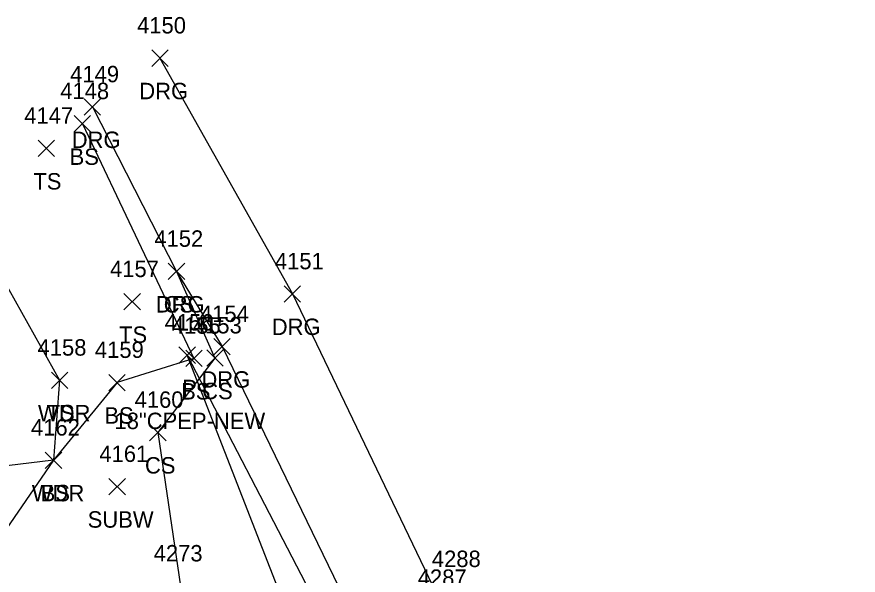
# Model space of a CAD drawing. Extents: x 49137 to 50946, y 9590 to 10709.
# Drawn here: x 50101.6 to 50204, y 10636.8 to 10704.8 of the extents above; entities that cross this region are included whole.
import ezdxf

# ---------------------------------------------------------------- set-up
doc = ezdxf.new("R2010")
doc.units = 0
for name, color, linetype in [('D_A', 7, 'Continuous'), ('D_C', 7, 'Continuous'), ('D_I', 7, 'Continuous'), ('D_TIC', 7, 'Continuous'), ('DCP', 7, 'Continuous'), ('L_A', 7, 'Continuous'), ('L_I', 7, 'Continuous'), ('L_TIC', 7, 'Continuous'), ('LAWA', 7, 'Continuous'), ('LELB', 7, 'Continuous'), ('R_A', 7, 'Continuous'), ('R_I', 7, 'Continuous'), ('R_TIC', 7, 'Continuous'), ('RDG', 7, 'Continuous'), ('U_A', 7, 'Continuous'), ('U_I', 7, 'Continuous'), ('U_TIC', 7, 'Continuous')]:
    doc.layers.add(name, color=color, linetype=linetype)

msp = doc.modelspace()

# ---------------------------------------------------------------- linework, layer by layer
at = {"layer": 'D_TIC'}
for points in [[(50121.34, 10662.61), (50123.34, 10664.61)], [(50123.34, 10662.61), (50121.34, 10664.61)]]:
    msp.add_lwpolyline(points, dxfattribs=at)
at = {"layer": 'DCP'}
msp.add_lwpolyline([(49941.69, 9827.48), (50059.34, 9808.37), (50181.4, 9733.09), (50281.74, 9743.29), (50422.72, 9892.52), (50122.34, 10663.61), (50179.93, 10552.61), (50179.64, 10394.45), (50122.34, 10285.07), (50121.56, 10284.35)], dxfattribs=at)
at = {"layer": 'L_TIC'}
for points in [[(50108.59, 10690.77), (50110.59, 10692.77)], [(50110.59, 10690.77), (50108.59, 10692.77)], [(50104.21, 10687.77), (50106.21, 10689.77)], [(50106.21, 10687.77), (50104.21, 10689.77)], [(50120.04, 10672.8), (50122.04, 10674.8)], [(50122.04, 10672.8), (50120.04, 10674.8)], [(50114.64, 10669.11), (50116.64, 10671.11)], [(50116.64, 10669.11), (50114.64, 10671.11)], [(50122.16, 10662.21), (50124.16, 10664.21)], [(50124.16, 10662.21), (50122.16, 10664.21)], [(50124.72, 10662.25), (50126.72, 10664.25)], [(50126.72, 10662.25), (50124.72, 10664.25)], [(50105.82, 10659.55), (50107.82, 10661.55)], [(50107.82, 10659.55), (50105.82, 10661.55)], [(50105.82, 10659.55), (50107.82, 10661.55)], [(50107.82, 10659.55), (50105.82, 10661.55)], [(50112.81, 10659.27), (50114.81, 10661.27)], [(50114.81, 10659.27), (50112.81, 10661.27)], [(50117.76, 10653.2), (50119.76, 10655.2)], [(50119.76, 10653.2), (50117.76, 10655.2)], [(50105.07, 10649.82), (50107.07, 10651.82)], [(50107.07, 10649.82), (50105.07, 10651.82)], [(50105.07, 10649.82), (50107.07, 10651.82)], [(50107.07, 10649.82), (50105.07, 10651.82)]]:
    msp.add_lwpolyline(points, dxfattribs=at)
at = {"layer": 'LAWA'}
msp.add_lwpolyline([(50094.44, 10682.64), (50106.82, 10660.55), (50106.07, 10650.82), (50096.35, 10649.67)], dxfattribs=at)
at = {"layer": 'LELB'}
for points in [[(50109.59, 10691.77), (50123.16, 10663.21), (50113.81, 10660.27), (50106.07, 10650.82), (50097.87, 10638.93), (50087.99, 10629.91)], [(50121.04, 10673.8), (50125.72, 10663.25), (50118.76, 10654.2), (50121.52, 10635.5), (50130.84, 10628.15), (50141.37, 10625.76), (50142.8, 10621.81), (50131.45, 10616.61), (50128.86, 10614.81), (50135.94, 10599.09), (50146.92, 10581.6), (50169.4, 10551.93), (50172.24, 10543.56), (50191.94, 10521.73), (50208.27, 10509.79)]]:
    msp.add_lwpolyline(points, dxfattribs=at)
at = {"layer": 'R_TIC'}
for points in [[(50118.02, 10698.76), (50120.02, 10700.76)], [(50120.02, 10698.76), (50118.02, 10700.76)], [(50109.8, 10692.82), (50111.8, 10694.82)], [(50111.8, 10692.82), (50109.8, 10694.82)], [(50120.04, 10672.8), (50122.04, 10674.8)], [(50122.04, 10672.8), (50120.04, 10674.8)], [(50134.14, 10670.06), (50136.14, 10672.06)], [(50136.14, 10670.06), (50134.14, 10672.06)], [(50125.58, 10663.65), (50127.58, 10665.65)], [(50127.58, 10663.65), (50125.58, 10665.65)]]:
    msp.add_lwpolyline(points, dxfattribs=at)
at = {"layer": 'RDG'}
for points in [[(50119.02, 10699.76), (50135.14, 10671.06), (50153.64, 10632.53), (50170.9, 10598.36), (50195.96, 10553.2), (50209.41, 10536.57), (50218.43, 10521.85), (50227.96, 10501.32), (50227.51, 10456.11), (50228.06, 10435.89), (50234.37, 10417.11), (50265.83, 10427.19)], [(50110.8, 10693.82), (50121.04, 10673.8), (50126.58, 10664.65), (50145.31, 10626.1), (50162.07, 10592.03), (50186.9, 10549.34), (50201.97, 10525.51), (50210.44, 10510.19), (50215.05, 10493.61), (50214.49, 10487.12), (50214.47, 10480.19), (50214.66, 10477.36), (50207.53, 10457)]]:
    msp.add_lwpolyline(points, dxfattribs=at)
at = {"layer": 'U_TIC'}
for points in [[(50112.82, 10646.61), (50114.82, 10648.61)], [(50114.82, 10646.61), (50112.82, 10648.61)]]:
    msp.add_lwpolyline(points, dxfattribs=at)

# ---------------------------------------------------------------- texts
at = {"layer": 'D_A'}
msp.add_text('P', height=2, dxfattribs=at).set_placement((50121.72, 10658.61))
at = {"layer": 'D_C'}
msp.add_text('18"CPEP-NEW', height=2, dxfattribs=at).set_placement((50113.49, 10654.61))
at = {"layer": 'D_I'}
for s, p in [('4156', (50119.59, 10666.61)), ('4288', (50152.11, 10637.82))]:
    msp.add_text(s, height=2, dxfattribs=at).set_placement(p)
at = {"layer": 'L_A'}
for s, p in [('BS', (50108.03, 10686.77)), ('TS', (50103.62, 10683.77)), ('CS', (50119.48, 10668.8)), ('TS', (50114.05, 10665.11)), ('BS', (50121.6, 10658.21)), ('CS', (50124.16, 10658.25)), ('WDR', (50104.18, 10655.55)), ('TS', (50105.23, 10655.55)), ('BS', (50112.26, 10655.27)), ('CS', (50117.2, 10649.2)), ('WDR', (50103.43, 10645.82)), ('BS', (50104.51, 10645.82))]:
    msp.add_text(s, height=2, dxfattribs=at).set_placement(p)
at = {"layer": 'L_I'}
for s, p in [('4148', (50106.89, 10694.77)), ('4147', (50102.51, 10691.77)), ('4152', (50118.34, 10676.8)), ('4157', (50112.95, 10673.11)), ('4155', (50120.47, 10666.21)), ('4153', (50123.03, 10666.25)), ('4158', (50104.13, 10663.55)), ('4158', (50104.13, 10663.55)), ('4159', (50111.11, 10663.27)), ('4160', (50115.94, 10657.2)), ('4162', (50103.33, 10653.82)), ('4162', (50103.33, 10653.82)), ('4273', (50118.26, 10638.5)), ('4273', (50118.26, 10638.5))]:
    msp.add_text(s, height=2, dxfattribs=at).set_placement(p)
at = {"layer": 'R_A'}
for p in [(50116.51, 10694.76), (50108.29, 10688.82), (50118.52, 10668.8), (50132.63, 10666.06), (50124.07, 10659.65)]:
    msp.add_text('DRG', height=2, dxfattribs=at).set_placement(p)
at = {"layer": 'R_I'}
for s, p in [('4150', (50116.24, 10702.76)), ('4149', (50108.1, 10696.82)), ('4152', (50118.34, 10676.8)), ('4151', (50133.01, 10674.06)), ('4154', (50123.89, 10667.65)), ('4287', (50150.39, 10635.53))]:
    msp.add_text(s, height=2, dxfattribs=at).set_placement(p)
at = {"layer": 'U_A'}
msp.add_text('SUBW', height=2, dxfattribs=at).set_placement((50110.23, 10642.61))
at = {"layer": 'U_I'}
msp.add_text('4161', height=2, dxfattribs=at).set_placement((50111.65, 10650.61))

doc.saveas('drawing.dxf')
